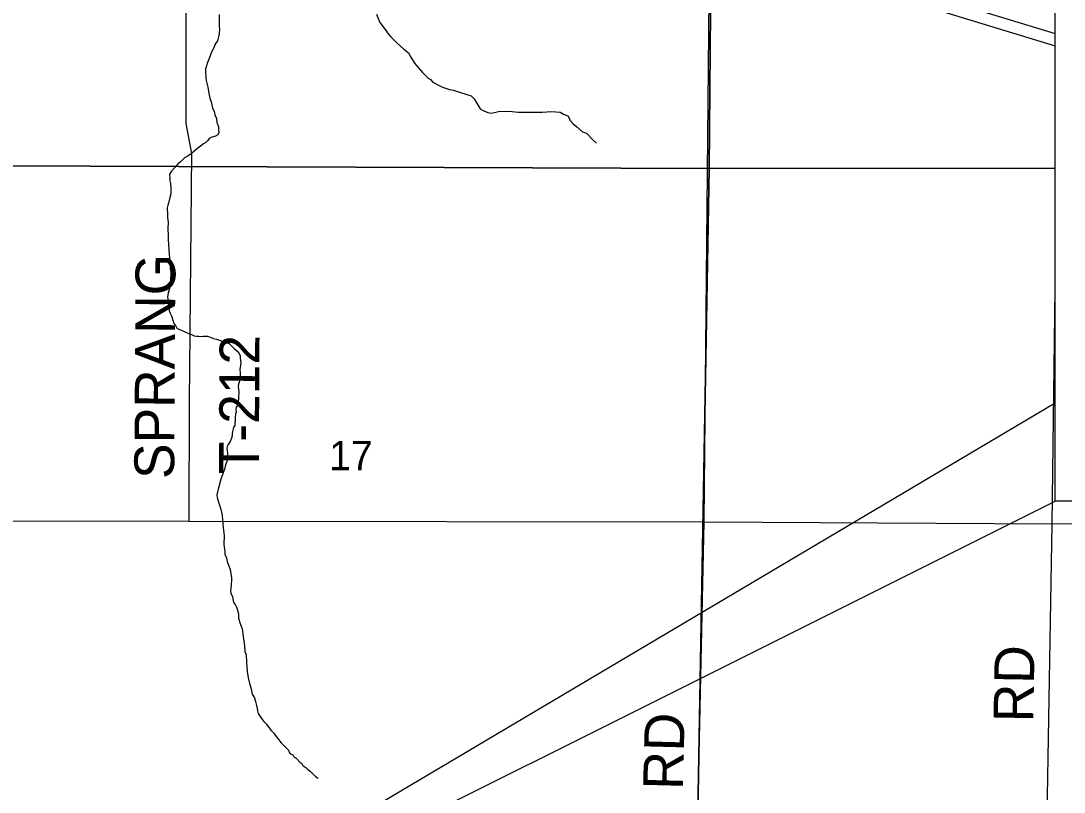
# Model space of a CAD drawing. Extents: x 0 to 34, y 0 to 22.
# Drawn here: x 27.011 to 28.499, y 17.024 to 18.124 of the extents above; entities that cross this region are included whole.
import ezdxf

# ---------------------------------------------------------------- set-up
doc = ezdxf.new("R2010")
doc.units = 0
for name, color, linetype in [('GM_X_County_Road', 7, 'Continuous'), ('GM_X_Minor_River', 7, 'Continuous'), ('GM_X_Rail_Line', 7, 'Continuous'), ('GM_X_Section', 7, 'Continuous'), ('GM_X_Section_Text', 7, 'Continuous'), ('GM_X_Township_Road', 7, 'Continuous'), ('GM_X_Township_Road_Text', 7, 'Continuous'), ('SH_Data', 7, 'Continuous')]:
    doc.layers.add(name, color=color, linetype=linetype)

msp = doc.modelspace()

# ---------------------------------------------------------------- linework, layer by layer
at = {"layer": 'GM_X_County_Road'}
for points in [[(26.8961, 17.4108), (27.2508, 17.4104), (27.9854, 17.4096)], [(27.9854, 17.4096), (28.4819, 17.4065), (28.9512, 17.4111), (29.2332, 17.4075)]]:
    msp.add_lwpolyline(points, dxfattribs=at)
at = {"layer": 'GM_X_Minor_River'}
for points in [[(27.2933, 18.1327), (27.2937, 18.1191), (27.2937, 18.1156), (27.294, 18.1118), (27.2935, 18.1065), (27.293, 18.1028), (27.291, 18.0952), (27.2886, 18.0922), (27.2875, 18.0896), (27.2855, 18.0843), (27.2823, 18.0783), (27.2807, 18.0738), (27.2783, 18.0678), (27.2767, 18.0644), (27.2755, 18.0595), (27.2742, 18.0553), (27.2738, 18.0523), (27.2741, 18.0489), (27.2744, 18.0462), (27.2747, 18.0428), (27.275, 18.039), (27.2757, 18.0352), (27.2771, 18.0291), (27.2788, 18.0204), (27.2799, 18.0162), (27.2802, 18.0135), (27.282, 18.0082), (27.283, 18.004), (27.2841, 17.9994), (27.2862, 17.9952), (27.2873, 17.9898)], [(27.5178, 18.1334), (27.5229, 18.1216), (27.5304, 18.1117), (27.5338, 18.1067), (27.5382, 18.1009), (27.5476, 18.0921), (27.557, 18.0837), (27.5634, 18.0783), (27.5671, 18.0722), (27.572, 18.0634), (27.5772, 18.0573), (27.5836, 18.05), (27.5907, 18.0431), (27.5948, 18.0404), (27.5982, 18.0362), (27.6065, 18.0319), (27.6122, 18.0292), (27.622, 18.026), (27.628, 18.0248), (27.6333, 18.0229), (27.6466, 18.0189), (27.653, 18.017), (27.6575, 18.0127), (27.6657, 17.9986), (27.6709, 17.9955), (27.6766, 17.9932), (27.6815, 17.992), (27.6899, 17.9942), (27.6941, 17.9949), (27.7032, 17.9948), (27.7074, 17.9951), (27.7157, 17.9939), (27.7202, 17.9935), (27.7263, 17.9938), (27.7544, 17.9935), (27.7677, 17.9945), (27.7798, 17.9936), (27.7847, 17.9909), (27.7911, 17.9885), (27.7948, 17.9813), (27.7986, 17.9771), (27.8038, 17.9725), (27.8117, 17.9655), (27.8174, 17.9636), (27.8271, 17.9536), (27.8316, 17.9494)], [(27.2873, 17.9898), (27.2898, 17.9845), (27.2904, 17.9784), (27.2915, 17.9757), (27.2926, 17.9727), (27.2925, 17.9693), (27.2928, 17.9647), (27.2916, 17.9613), (27.2881, 17.9595), (27.2828, 17.9581), (27.279, 17.9559), (27.2774, 17.9533), (27.2747, 17.9506), (27.2713, 17.9484), (27.2605, 17.9403), (27.2539, 17.9348), (27.2493, 17.9314), (27.244, 17.9285), (27.2382, 17.9229), (27.2343, 17.9196), (27.2254, 17.9095), (27.2227, 17.905), (27.2229, 17.8986), (27.2232, 17.8959), (27.2239, 17.8921), (27.2245, 17.8853), (27.2244, 17.8788), (27.2239, 17.8754), (27.2231, 17.872), (27.221, 17.8637), (27.2202, 17.8611), (27.2194, 17.8573), (27.2193, 17.8539), (27.2196, 17.8505), (27.2199, 17.8436), (27.2205, 17.8368), (27.2203, 17.8273), (27.2208, 17.8175), (27.2207, 17.8102), (27.2214, 17.8064), (27.2219, 17.7962), (27.2222, 17.7913), (27.2228, 17.7856), (27.2234, 17.7798), (27.2237, 17.7745), (27.2236, 17.77), (27.2243, 17.7654), (27.224, 17.7529), (27.2231, 17.745), (27.2227, 17.7423), (27.2215, 17.7389), (27.2206, 17.7355), (27.2198, 17.7302), (27.2201, 17.7272), (27.22, 17.7234), (27.2207, 17.7207), (27.221, 17.7173), (27.2217, 17.7139), (27.222, 17.7108), (27.2234, 17.707), (27.2253, 17.7032), (27.2274, 17.6971), (27.2288, 17.6921), (27.2314, 17.6894), (27.2332, 17.6856), (27.2358, 17.684), (27.2392, 17.6828), (27.2467, 17.6792), (27.2512, 17.6773), (27.2538, 17.6765), (27.258, 17.6749), (27.261, 17.6744), (27.2644, 17.674), (27.2674, 17.6739), (27.2705, 17.6742), (27.2769, 17.6741), (27.2822, 17.6725), (27.2852, 17.6709), (27.2897, 17.6697), (27.2938, 17.6684), (27.2976, 17.6672), (27.3077, 17.6636), (27.3114, 17.6601), (27.3151, 17.6566), (27.3189, 17.6535), (27.3218, 17.6493), (27.3233, 17.6462), (27.3236, 17.6432), (27.3239, 17.639), (27.3242, 17.6364), (27.3233, 17.6295), (27.3232, 17.6269), (27.3235, 17.6216), (27.3234, 17.6185), (27.323, 17.6151), (27.3229, 17.6121), (27.3221, 17.6087), (27.3213, 17.6057), (27.3208, 17.6023), (27.3211, 17.5981), (27.3214, 17.5951)], [(27.3214, 17.5951), (27.3212, 17.5856), (27.3199, 17.5758), (27.3179, 17.5728), (27.3175, 17.5694), (27.3178, 17.5659), (27.317, 17.5633), (27.3161, 17.5576), (27.3159, 17.5466), (27.3139, 17.544), (27.3127, 17.538), (27.3122, 17.5349), (27.3122, 17.5319), (27.3113, 17.5285), (27.3093, 17.524), (27.3062, 17.5199), (27.3047, 17.5169), (27.3046, 17.5139), (27.3049, 17.5104), (27.3052, 17.5078), (27.3055, 17.5017), (27.3054, 17.4983), (27.3046, 17.4956), (27.3026, 17.4908), (27.301, 17.4847), (27.2985, 17.4779), (27.2957, 17.4704), (27.2929, 17.4595), (27.292, 17.4561), (27.2912, 17.4523), (27.2903, 17.4478), (27.2906, 17.444), (27.2935, 17.4348), (27.2945, 17.4317), (27.296, 17.4268), (27.297, 17.423), (27.2977, 17.4184), (27.2983, 17.4127), (27.2989, 17.4062), (27.2992, 17.4013), (27.2999, 17.3975), (27.3002, 17.3933), (27.3005, 17.3899), (27.3002, 17.377), (27.3015, 17.3671), (27.3018, 17.3633), (27.304, 17.3576), (27.305, 17.353), (27.3068, 17.3477), (27.3093, 17.3416), (27.3103, 17.3351), (27.311, 17.3298), (27.3109, 17.3252), (27.3104, 17.3214), (27.3104, 17.3184), (27.3098, 17.3116), (27.3101, 17.3078), (27.3123, 17.3024), (27.314, 17.2944), (27.3162, 17.2917), (27.3184, 17.2879), (27.3198, 17.2833), (27.3209, 17.2784), (27.3211, 17.2719), (27.3222, 17.2692), (27.3225, 17.2666), (27.324, 17.2631), (27.3247, 17.2605), (27.3265, 17.257), (27.3278, 17.246), (27.3298, 17.2327), (27.3303, 17.2243), (27.3321, 17.2197), (27.3327, 17.2087), (27.3335, 17.1962), (27.3349, 17.187), (27.337, 17.1787), (27.3387, 17.1733), (27.3408, 17.1638), (27.3441, 17.1584), (27.3455, 17.1534), (27.3469, 17.1477), (27.3476, 17.1432), (27.3483, 17.1401), (27.3489, 17.1359), (27.3512, 17.1332), (27.3537, 17.129), (27.3574, 17.1248), (27.3604, 17.1213), (27.363, 17.1182), (27.3652, 17.1151), (27.3674, 17.1124), (27.3715, 17.1082), (27.3733, 17.1051), (27.3766, 17.1009), (27.3821, 17.0943), (27.3922, 17.0839), (27.3936, 17.08), (27.3962, 17.0781), (27.3992, 17.0765), (27.4007, 17.0738)], [(27.4007, 17.0738), (27.4033, 17.0726), (27.4088, 17.0668), (27.4114, 17.0649), (27.4129, 17.0618), (27.417, 17.0591), (27.4196, 17.0568), (27.4237, 17.0533), (27.4285, 17.0486), (27.4311, 17.0463), (27.4345, 17.0439)]]:
    msp.add_lwpolyline(points, dxfattribs=at)
at = {"layer": 'GM_X_Rail_Line'}
for points in [[(24.1704, 19.5327), (24.2425, 19.4909), (24.3878, 19.4135), (24.5787, 19.3195), (24.7175, 19.2589), (24.8405, 19.2105), (24.9746, 19.1639), (25.4423, 19.0168), (26.3104, 18.7542), (27.1506, 18.4971), (27.9899, 18.2401), (28.4862, 18.088)], [(26.9875, 18.5627), (27.1965, 18.4991), (27.42, 18.4308), (27.5908, 18.3787), (27.749, 18.3302), (27.8567, 18.2973), (27.9349, 18.2735), (27.9943, 18.2554), (28.4862, 18.1059)]]:
    msp.add_lwpolyline(points, dxfattribs=at)
at = {"layer": 'GM_X_Section'}
for points in [[(28.001, 18.9217), (27.9928, 17.9132), (26.984, 17.9172), (27.0012, 18.9192)], [(27.9928, 17.9132), (27.9749, 16.9131), (26.974, 16.9197), (26.984, 17.9172)]]:
    msp.add_lwpolyline(points, close=True, dxfattribs=at)
for points in [[(28.4862, 17.9139), (27.9928, 17.9132), (28.001, 18.9217), (29.0034, 18.9139), (28.9945, 18.1387)], [(28.9884, 17.4387), (28.9846, 16.9148), (27.9749, 16.9131), (27.9928, 17.9132), (28.4862, 17.9139)]]:
    msp.add_lwpolyline(points, dxfattribs=at)
at = {"layer": 'GM_X_Township_Road'}
for p, q in [((27.9854, 17.4096), (27.9934, 18.2405)), ((28.4819, 17.4065), (28.4862, 17.7419)), ((27.9618, 16.2967), (27.9854, 17.4096)), ((28.4643, 16.4064), (28.4819, 17.4065))]:
    msp.add_line(p, q, dxfattribs=at)
for points in [[(27.2521, 17.6804), (27.2543, 17.9349), (27.2463, 17.9776), (27.2464, 18.2704), (27.2497, 18.2829), (27.2429, 18.3126), (27.216, 18.3814), (27.1953, 18.4923)], [(27.2508, 17.4104), (27.2513, 17.581), (27.2521, 17.6784), (27.2521, 17.6804)]]:
    msp.add_lwpolyline(points, dxfattribs=at)
at = {"layer": 'SH_Data'}
for points in [[(28.4862, 18.1387), (29.9962, 18.1387), (29.9962, 17.4387), (28.4862, 17.4387)], [(28.4862, 17.5787), (26.9847, 16.6887), (28.4862, 17.4387)]]:
    msp.add_lwpolyline(points, close=True, dxfattribs=at)

# ---------------------------------------------------------------- texts
at = {"layer": 'GM_X_Section_Text'}
msp.add_text('17', height=0.04186, rotation=0, dxfattribs=at).set_placement((27.4503, 17.483))
at = {"layer": 'GM_X_Township_Road_Text'}
for s, rotation, p in [('SPRANG', 89.6516, (27.2292, 17.4704)), ('T-212', 89.7193, (27.3501, 17.4773)), ('RD', 89.0128, (28.455, 17.1232)), ('RD', 88.5175, (27.955, 17.0267))]:
    msp.add_text(s, height=0.05682, rotation=rotation, dxfattribs=at).set_placement(p)

doc.saveas('drawing.dxf')
